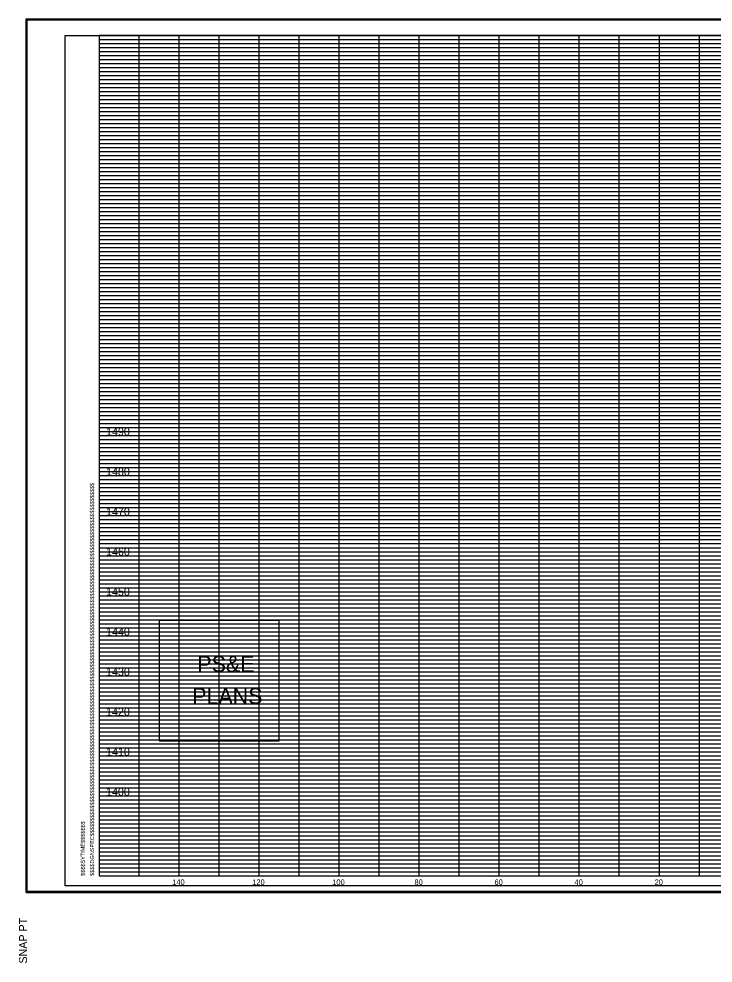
# Model space of a CAD drawing. Extents: x 980 to 2064, y 978 to 2267.
# Drawn here: x 979.9 to 1153.4, y 1758.2 to 1994.1 of the extents above; entities that cross this region are included whole.
import ezdxf

# ---------------------------------------------------------------- set-up
doc = ezdxf.new("R2010")
doc.units = 0
for name, color, linetype in [('Default', 7, 'Continuous'), ('DESIGN - SHEET - Corner Text', 7, 'Continuous'), ('DESIGN - SHEET - Light Grid', 7, 'Continuous'), ('DESIGN - SHEET - Linework', 7, 'Continuous'), ('DESIGN - SHEET - Plot Shape', 7, 'Continuous')]:
    doc.layers.add(name, color=color, linetype=linetype)

# ---------------------------------------------------------------- blocks, each defined once
blk = doc.blocks.new('XSTSHT')
at = {"layer": 'DESIGN - SHEET - Light Grid'}
for p, q in [((0, 20.9), (8, 20.9)), ((0, 20.8), (8, 20.8)), ((8, 20.9), (16, 20.9)), ((8, 20.8), (16, 20.8)), ((0, 20.7), (8, 20.7)), ((0, 20.6), (8, 20.6)), ((8, 20.7), (16, 20.7)), ((8, 20.6), (16, 20.6)), ((0, 20.5), (8, 20.5)), ((0, 20.4), (8, 20.4)), ((0, 20.3), (8, 20.3)), ((8, 20.5), (16, 20.5)), ((8, 20.4), (16, 20.4)), ((8, 20.3), (16, 20.3)), ((0, 20.2), (8, 20.2)), ((0, 20.1), (8, 20.1)), ((8, 20.2), (16, 20.2)), ((8, 20.1), (16, 20.1)), ((0, 19.9), (8, 19.9)), ((8, 19.9), (16, 19.9)), ((0, 19.8), (8, 19.8)), ((0, 19.7), (8, 19.7)), ((0, 19.6), (8, 19.6)), ((8, 19.8), (16, 19.8)), ((8, 19.7), (16, 19.7)), ((8, 19.6), (16, 19.6)), ((0, 19.5), (8, 19.5)), ((0, 19.4), (8, 19.4)), ((8, 19.5), (16, 19.5)), ((8, 19.4), (16, 19.4)), ((0, 19.3), (8, 19.3)), ((0, 19.2), (8, 19.2)), ((8, 19.3), (16, 19.3)), ((8, 19.2), (16, 19.2)), ((0, 19.1), (8, 19.1)), ((0, 18.9), (8, 18.9)), ((8, 19.1), (16, 19.1)), ((8, 18.9), (16, 18.9)), ((0, 18.8), (8, 18.8)), ((0, 18.7), (8, 18.7)), ((8, 18.8), (16, 18.8)), ((8, 18.7), (16, 18.7)), ((0, 18.6), (8, 18.6)), ((0, 18.5), (8, 18.5)), ((8, 18.6), (16, 18.6)), ((8, 18.5), (16, 18.5)), ((0, 18.4), (8, 18.4)), ((0, 18.3), (8, 18.3)), ((0, 18.2), (8, 18.2)), ((8, 18.4), (16, 18.4)), ((8, 18.3), (16, 18.3)), ((8, 18.2), (16, 18.2)), ((0, 18.1), (8, 18.1)), ((8, 18.1), (16, 18.1)), ((0, 17.9), (8, 17.9)), ((0, 17.8), (8, 17.8)), ((0, 17.7), (8, 17.7)), ((8, 17.9), (16, 17.9)), ((8, 17.8), (16, 17.8)), ((8, 17.7), (16, 17.7)), ((0, 17.6), (8, 17.6)), ((0, 17.5), (8, 17.5)), ((8, 17.6), (16, 17.6)), ((8, 17.5), (16, 17.5)), ((0, 17.4), (8, 17.4)), ((0, 17.3), (8, 17.3)), ((8, 17.4), (16, 17.4)), ((8, 17.3), (16, 17.3)), ((0, 17.2), (8, 17.2)), ((0, 17.1), (8, 17.1)), ((8, 17.2), (16, 17.2)), ((8, 17.1), (16, 17.1)), ((0, 16.9), (8, 16.9)), ((0, 16.8), (8, 16.8)), ((8, 16.9), (16, 16.9)), ((8, 16.8), (16, 16.8)), ((0, 16.7), (8, 16.7)), ((0, 16.6), (8, 16.6)), ((8, 16.7), (16, 16.7)), ((8, 16.6), (16, 16.6)), ((0, 16.5), (8, 16.5)), ((0, 16.4), (8, 16.4)), ((0, 16.3), (8, 16.3)), ((8, 16.5), (16, 16.5)), ((8, 16.4), (16, 16.4)), ((8, 16.3), (16, 16.3)), ((0, 16.2), (8, 16.2)), ((0, 16.1), (8, 16.1)), ((8, 16.2), (16, 16.2)), ((8, 16.1), (16, 16.1)), ((0, 15.9), (8, 15.9)), ((8, 15.9), (16, 15.9)), ((0, 15.8), (8, 15.8)), ((0, 15.7), (8, 15.7)), ((0, 15.6), (8, 15.6)), ((8, 15.8), (16, 15.8)), ((8, 15.7), (16, 15.7)), ((8, 15.6), (16, 15.6)), ((0, 15.5), (8, 15.5)), ((0, 15.4), (8, 15.4)), ((8, 15.5), (16, 15.5)), ((8, 15.4), (16, 15.4)), ((0, 15.3), (8, 15.3)), ((0, 15.2), (8, 15.2)), ((8, 15.3), (16, 15.3)), ((8, 15.2), (16, 15.2)), ((0, 15.1), (8, 15.1)), ((0, 14.9), (8, 14.9)), ((8, 15.1), (16, 15.1)), ((8, 14.9), (16, 14.9)), ((0, 14.8), (8, 14.8)), ((0, 14.7), (8, 14.7)), ((8, 14.8), (16, 14.8)), ((8, 14.7), (16, 14.7)), ((0, 14.6), (8, 14.6)), ((0, 14.5), (8, 14.5)), ((0, 14.4), (8, 14.4)), ((8, 14.6), (16, 14.6)), ((8, 14.5), (16, 14.5)), ((8, 14.4), (16, 14.4)), ((0, 14.3), (8, 14.3)), ((0, 14.2), (8, 14.2)), ((8, 14.3), (16, 14.3)), ((8, 14.2), (16, 14.2)), ((0, 14.1), (8, 14.1)), ((8, 14.1), (16, 14.1)), ((0, 13.9), (8, 13.9)), ((0, 13.8), (8, 13.8)), ((0, 13.7), (8, 13.7)), ((8, 13.9), (16, 13.9)), ((8, 13.8), (16, 13.8)), ((8, 13.7), (16, 13.7)), ((0, 13.6), (8, 13.6)), ((0, 13.5), (8, 13.5)), ((8, 13.6), (16, 13.6)), ((8, 13.5), (16, 13.5)), ((0, 13.4), (8, 13.4)), ((0, 13.3), (8, 13.3)), ((8, 13.4), (16, 13.4)), ((8, 13.3), (16, 13.3)), ((0, 13.2), (8, 13.2)), ((0, 13.1), (8, 13.1)), ((8, 13.2), (16, 13.2)), ((8, 13.1), (16, 13.1)), ((0, 12.9), (8, 12.9)), ((0, 12.8), (8, 12.8)), ((8, 12.9), (16, 12.9)), ((8, 12.8), (16, 12.8)), ((0, 12.7), (8, 12.7)), ((0, 12.6), (8, 12.6)), ((8, 12.7), (16, 12.7)), ((8, 12.6), (16, 12.6)), ((0, 12.5), (8, 12.5)), ((0, 12.4), (8, 12.4)), ((0, 12.3), (8, 12.3)), ((8, 12.5), (16, 12.5)), ((8, 12.4), (16, 12.4)), ((8, 12.3), (16, 12.3)), ((0, 12.2), (8, 12.2)), ((0, 12.1), (8, 12.1)), ((8, 12.2), (16, 12.2)), ((8, 12.1), (16, 12.1)), ((0, 11.9), (8, 11.9)), ((0, 11.8), (8, 11.8)), ((8, 11.9), (16, 11.9)), ((8, 11.8), (16, 11.8)), ((0, 11.7), (8, 11.7)), ((0, 11.6), (8, 11.6)), ((8, 11.7), (16, 11.7)), ((8, 11.6), (16, 11.6)), ((0, 11.5), (8, 11.5)), ((0, 11.4), (8, 11.4)), ((8, 11.5), (16, 11.5)), ((8, 11.4), (16, 11.4)), ((0, 11.3), (8, 11.3)), ((0, 11.2), (8, 11.2)), ((0, 11.1), (8, 11.1)), ((8, 11.3), (16, 11.3)), ((8, 11.2), (16, 11.2)), ((8, 11.1), (16, 11.1)), ((0, 10.9), (8, 10.9)), ((8, 10.9), (16, 10.9)), ((0, 10.8), (8, 10.8)), ((0, 10.7), (8, 10.7)), ((8, 10.8), (16, 10.8)), ((8, 10.7), (16, 10.7)), ((0, 10.6), (8, 10.6)), ((0, 10.5), (8, 10.5)), ((0, 10.4), (8, 10.4)), ((8, 10.6), (16, 10.6)), ((8, 10.5), (16, 10.5)), ((8, 10.4), (16, 10.4)), ((0, 10.3), (8, 10.3)), ((0, 10.2), (8, 10.2)), ((8, 10.3), (16, 10.3)), ((8, 10.2), (16, 10.2)), ((0, 10.1), (8, 10.1)), ((8, 10.1), (16, 10.1)), ((0, 9.9), (8, 9.9)), ((0, 9.8), (8, 9.8)), ((0, 9.7), (8, 9.7)), ((8, 9.9), (16, 9.9)), ((8, 9.8), (16, 9.8)), ((8, 9.7), (16, 9.7)), ((0, 9.6), (8, 9.6)), ((0, 9.5), (8, 9.5)), ((8, 9.6), (16, 9.6)), ((8, 9.5), (16, 9.5)), ((0, 9.4), (8, 9.4)), ((0, 9.3), (8, 9.3)), ((8, 9.4), (16, 9.4)), ((8, 9.3), (16, 9.3)), ((0, 9.2), (8, 9.2)), ((0, 9.1), (8, 9.1)), ((8, 9.2), (16, 9.2)), ((8, 9.1), (16, 9.1)), ((0, 8.9), (8, 8.9)), ((0, 8.8), (8, 8.8)), ((8, 8.9), (16, 8.9)), ((8, 8.8), (16, 8.8)), ((0, 8.7), (8, 8.7)), ((0, 8.6), (8, 8.6)), ((0, 8.5), (8, 8.5)), ((8, 8.7), (16, 8.7)), ((8, 8.6), (16, 8.6)), ((8, 8.5), (16, 8.5)), ((0, 8.4), (8, 8.4)), ((0, 8.3), (8, 8.3)), ((8, 8.4), (16, 8.4)), ((8, 8.3), (16, 8.3)), ((0, 8.2), (8, 8.2)), ((0, 8.1), (8, 8.1)), ((8, 8.2), (16, 8.2)), ((8, 8.1), (16, 8.1)), ((0, 7.9), (8, 7.9)), ((0, 7.8), (8, 7.8)), ((8, 7.9), (16, 7.9)), ((8, 7.8), (16, 7.8)), ((0, 7.7), (8, 7.7)), ((0, 7.6), (8, 7.6)), ((8, 7.7), (16, 7.7)), ((8, 7.6), (16, 7.6)), ((0, 7.5), (8, 7.5)), ((0, 7.4), (8, 7.4)), ((8, 7.5), (16, 7.5)), ((8, 7.4), (16, 7.4)), ((0, 7.3), (8, 7.3)), ((0, 7.2), (8, 7.2)), ((0, 7.1), (8, 7.1)), ((8, 7.3), (16, 7.3)), ((8, 7.2), (16, 7.2)), ((8, 7.1), (16, 7.1)), ((0, 6.9), (8, 6.9)), ((8, 6.9), (16, 6.9)), ((0, 6.8), (8, 6.8)), ((0, 6.7), (8, 6.7)), ((8, 6.8), (16, 6.8)), ((8, 6.7), (16, 6.7)), ((0, 6.6), (8, 6.6)), ((0, 6.5), (8, 6.5)), ((0, 6.4), (8, 6.4)), ((8, 6.6), (16, 6.6)), ((8, 6.5), (16, 6.5)), ((8, 6.4), (16, 6.4)), ((0, 6.3), (8, 6.3)), ((0, 6.2), (8, 6.2)), ((8, 6.3), (16, 6.3)), ((8, 6.2), (16, 6.2)), ((0, 6.1), (8, 6.1)), ((0, 5.9), (8, 5.9)), ((8, 6.1), (16, 6.1)), ((8, 5.9), (16, 5.9)), ((0, 5.8), (8, 5.8)), ((0, 5.7), (8, 5.7)), ((8, 5.8), (16, 5.8)), ((8, 5.7), (16, 5.7)), ((0, 5.6), (8, 5.6)), ((0, 5.5), (8, 5.5)), ((8, 5.6), (16, 5.6)), ((8, 5.5), (16, 5.5)), ((0, 5.4), (8, 5.4)), ((0, 5.3), (8, 5.3)), ((0, 5.2), (8, 5.2)), ((8, 5.4), (16, 5.4)), ((8, 5.3), (16, 5.3)), ((8, 5.2), (16, 5.2)), ((0, 5.1), (8, 5.1)), ((8, 5.1), (16, 5.1)), ((0, 4.9), (8, 4.9)), ((0, 4.8), (8, 4.8)), ((8, 4.9), (16, 4.9)), ((8, 4.8), (16, 4.8)), ((0, 4.7), (8, 4.7)), ((0, 4.6), (8, 4.6)), ((0, 4.5), (8, 4.5)), ((8, 4.7), (16, 4.7)), ((8, 4.6), (16, 4.6)), ((8, 4.5), (16, 4.5)), ((0, 4.4), (8, 4.4)), ((0, 4.3), (8, 4.3)), ((8, 4.4), (16, 4.4)), ((8, 4.3), (16, 4.3)), ((0, 4.2), (8, 4.2)), ((0, 4.1), (8, 4.1)), ((8, 4.2), (16, 4.2)), ((8, 4.1), (16, 4.1)), ((0, 3.9), (8, 3.9)), ((0, 3.8), (8, 3.8)), ((8, 3.9), (16, 3.9)), ((8, 3.8), (16, 3.8)), ((0, 3.7), (8, 3.7)), ((0, 3.6), (8, 3.6)), ((8, 3.7), (16, 3.7)), ((8, 3.6), (16, 3.6)), ((0, 3.5), (8, 3.5)), ((0, 3.4), (8, 3.4)), ((8, 3.5), (16, 3.5)), ((8, 3.4), (16, 3.4)), ((0, 3.3), (8, 3.3)), ((0, 3.2), (8, 3.2)), ((0, 3.1), (8, 3.1)), ((8, 3.3), (16, 3.3)), ((8, 3.2), (16, 3.2)), ((8, 3.1), (16, 3.1)), ((0, 2.9), (8, 2.9)), ((8, 2.9), (16, 2.9)), ((0, 2.8), (8, 2.8)), ((0, 2.7), (8, 2.7)), ((0, 2.6), (8, 2.6)), ((8, 2.8), (16, 2.8)), ((8, 2.7), (16, 2.7)), ((8, 2.6), (16, 2.6)), ((0, 2.5), (8, 2.5)), ((0, 2.4), (8, 2.4)), ((8, 2.5), (16, 2.5)), ((8, 2.4), (16, 2.4)), ((0, 2.3), (8, 2.3)), ((0, 2.2), (8, 2.2)), ((8, 2.3), (16, 2.3)), ((8, 2.2), (16, 2.2)), ((0, 2.1), (8, 2.1)), ((0, 1.9), (8, 1.9)), ((8, 2.1), (16, 2.1)), ((8, 1.9), (16, 1.9)), ((0, 1.8), (8, 1.8)), ((0, 1.7), (8, 1.7)), ((8, 1.8), (16, 1.8)), ((8, 1.7), (16, 1.7)), ((0, 1.6), (8, 1.6)), ((0, 1.5), (8, 1.5)), ((8, 1.6), (16, 1.6)), ((8, 1.5), (16, 1.5)), ((0, 1.4), (8, 1.4)), ((0, 1.3), (8, 1.3)), ((0, 1.2), (8, 1.2)), ((8, 1.4), (16, 1.4)), ((8, 1.3), (16, 1.3)), ((8, 1.2), (16, 1.2)), ((0, 1.1), (8, 1.1)), ((8, 1.1), (16, 1.1)), ((0, 0.9), (8, 0.9)), ((0, 0.8), (8, 0.8)), ((8, 0.9), (16, 0.9)), ((8, 0.8), (16, 0.8)), ((0, 0.7), (8, 0.7)), ((0, 0.6), (8, 0.6)), ((0, 0.5), (8, 0.5)), ((8, 0.7), (16, 0.7)), ((8, 0.6), (16, 0.6)), ((8, 0.5), (16, 0.5)), ((0, 0.4), (8, 0.4)), ((0, 0.3), (8, 0.3)), ((8, 0.4), (16, 0.4)), ((8, 0.3), (16, 0.3)), ((0, 0.2), (8, 0.2)), ((0, 0.1), (8, 0.1)), ((8, 0.2), (16, 0.2)), ((8, 0.1), (16, 0.1))]:
    blk.add_line(p, q, dxfattribs=at)
at = {"layer": 'DESIGN - SHEET - Linework'}
for p, q in [((-1.823, -0.414), (-1.823, 21.414)), ((-1.823, 21.414), (32.217, 21.414)), ((1, 0), (1, 21)), ((2, 0), (2, 21)), ((3, 0), (3, 21)), ((4, 0), (4, 21)), ((5, 0), (5, 21)), ((6, 0), (6, 21)), ((7, 0), (7, 21)), ((8, 0), (8, 21)), ((9, 0), (9, 21)), ((10, 0), (10, 21)), ((11, 0), (11, 21)), ((12, 0), (12, 21)), ((13, 0), (13, 21)), ((14, 0), (14, 21)), ((15, 0), (15, 21)), ((0, 20), (28, 20)), ((0, 19), (32, 19)), ((0, 18), (32, 18)), ((0, 17), (32, 17)), ((0, 16), (32, 16)), ((0, 15), (32, 15)), ((0, 14), (32, 14)), ((0, 13), (32, 13)), ((0, 12), (32, 12)), ((0, 11), (32, 11)), ((0, 10), (32, 10)), ((0, 9), (32, 9)), ((0, 8), (32, 8)), ((0, 7), (32, 7)), ((0, 6), (32, 6)), ((0, 5), (32, 5)), ((0, 4), (32, 4)), ((0, 3), (32, 3)), ((0, 2), (32, 2)), ((0, 1), (32, 1)), ((-1.823, -0.414), (32.217, -0.414))]:
    blk.add_line(p, q, dxfattribs=at)
blk.add_lwpolyline([(0, 21), (0, 0), (32, 0), (32, 21), (0, 21)], dxfattribs=at)
at = {"layer": 'DESIGN - SHEET - Plot Shape'}
for points in [[(-1.803, 21.394), (32.197, 21.394), (32.197, -0.394), (-1.803, -0.394)], [(-0.85, 21), (32, 21), (32, -0.25), (-0.85, -0.25)]]:
    blk.add_lwpolyline(points, close=True, dxfattribs=at)
at = {"layer": 'DESIGN - SHEET - Corner Text'}
for s, height, p in [('$$$$DGNSPEC$$$$$$$$$$$$$$$$$$$$$$$$$$$$$$$$$$$$$$$$$$$$$$$$$$$$$$$$$$$$$$$$$$$$$$$$$$$$$$$$$$$$$$$$$$$$$$$$$$$$$$$$$$$$$$$$$$$', 0.100002, (-0.126, 0)), ('$$$$SYTIME$$$$$$$', 0.1, (-0.358, 0)), ('SNAP PT  ', 0.2, (-1.803, -2.194))]:
    blk.add_text(s, height=height, rotation=90, dxfattribs=at).set_placement(p)

msp = doc.modelspace()

# ---------------------------------------------------------------- linework, layer by layer
at = {"layer": 'DESIGN - SHEET - Corner Text'}
msp.add_lwpolyline([(1015.03, 1843.76), (1015.03, 1813.76), (1045.03, 1813.76), (1045.03, 1843.76)], close=True, dxfattribs=at)

# ---------------------------------------------------------------- block references
at = {"layer": 'Default', "xscale": 10, "yscale": 10}
msp.add_blockref('XSTSHT', (1000, 1780), dxfattribs=at)

# ---------------------------------------------------------------- texts
at = {"layer": 'Default'}
for s, height, p in [('     1490     ', 2, (998.01, 1890)), ('     1480     ', 2, (998.01, 1880)), ('     1470     ', 2, (998.01, 1870)), ('     1460     ', 2, (998.01, 1860)), ('     1450     ', 2, (998.01, 1850)), ('     1440     ', 2, (998.01, 1840)), ('     1430     ', 2, (998.01, 1830)), ('     1420     ', 2, (998.01, 1820)), ('     1410     ', 2, (998.01, 1810)), ('     1400     ', 2, (998.01, 1800)), ('     140     ', 1.4, (1015.65, 1777.7)), ('     120     ', 1.4, (1035.65, 1777.7)), ('     100     ', 1.4, (1055.65, 1777.7)), ('     80     ', 1.4, (1076.2, 1777.7)), ('     60     ', 1.4, (1096.2, 1777.7)), ('     40     ', 1.4, (1116.2, 1777.7)), ('     20     ', 1.4, (1136.2, 1777.7))]:
    msp.add_text(s, height=height, dxfattribs=at).set_placement(p)
at = {"layer": 'DESIGN - SHEET - Corner Text'}
for s, p in [('PS&E', (1024.55, 1830.94)), ('PLANS', (1023.27, 1822.94))]:
    msp.add_text(s, height=4, dxfattribs=at).set_placement(p)

doc.saveas('drawing.dxf')
